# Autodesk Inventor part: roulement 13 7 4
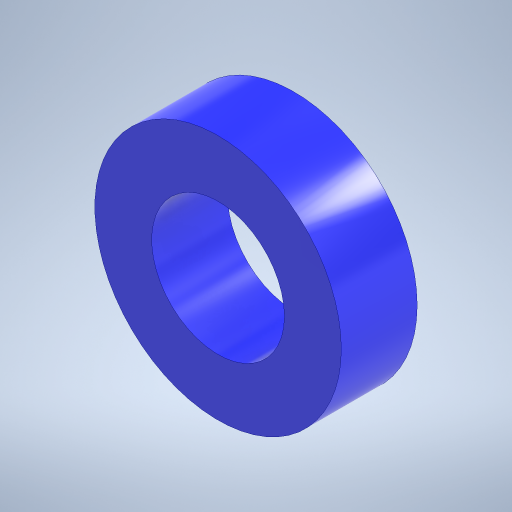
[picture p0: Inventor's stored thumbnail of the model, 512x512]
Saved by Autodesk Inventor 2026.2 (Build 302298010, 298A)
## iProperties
Created: 2025-06
Part Number: roulement 13 7 4
Material: Générique
Document SubType Name: Modeling
Designer: mel
Density: 1 g/cm^3
Appearance: Bleu - Peinture murale - Brillant
Author: mel
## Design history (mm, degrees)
sketch "Esquisse1"
  geometry: C1 r 6.5 at (0, 0); C2 r 3.5 at (0, 0); 1 further point
  constraints: 2 centre point, 2 coincident
  dimensions: "d0" = 13 diameter of C1; "d1" = 7 diameter of C2
extrude "Extrusion1" new body sketch "Esquisse1" distance "d2" = 4; taper "d3" = 0 deg
node "Solide1"
